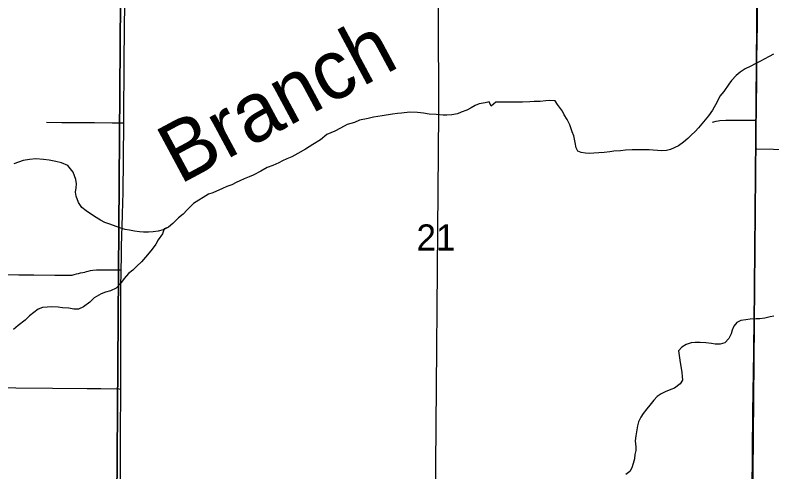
# Model space of a CAD drawing. Extents: x 0 to 34, y 0 to 22.
# Drawn here: x 6.452 to 7.662, y 16.502 to 17.233 of the extents above; entities that cross this region are included whole.
import ezdxf

# ---------------------------------------------------------------- set-up
doc = ezdxf.new("R2010")
doc.units = 0
for name, color, linetype in [('GM_X_County_Road', 7, 'Continuous'), ('GM_X_Major_River', 7, 'Continuous'), ('GM_X_Major_River_Text', 7, 'Continuous'), ('GM_X_Minor_River', 7, 'Continuous'), ('GM_X_Rail_Line', 7, 'Continuous'), ('GM_X_Section', 7, 'Continuous'), ('GM_X_Section_Text', 7, 'Continuous'), ('GM_X_Township_Road', 7, 'Continuous')]:
    doc.layers.add(name, color=color, linetype=linetype)

msp = doc.modelspace()

# ---------------------------------------------------------------- linework, layer by layer
at = {"layer": 'GM_X_County_Road'}
for points in [[(7.6367, 17.065), (7.6366, 17.0726), (7.6373, 17.1192), (7.6377, 17.1626), (7.6387, 17.2186), (7.6392, 17.3115), (7.6396, 17.3767), (7.6402, 17.4023)], [(7.6362, 17.0194), (7.6362, 17.0263), (7.6367, 17.065)], [(7.6291, 16.3875), (7.6291, 16.399), (7.63, 16.4704), (7.6314, 16.5977), (7.6327, 16.694), (7.6332, 16.7499), (7.6341, 16.8182), (7.6347, 16.8648), (7.6351, 16.9176), (7.6358, 16.9672), (7.6359, 16.9859), (7.6362, 17.0194)]]:
    msp.add_lwpolyline(points, dxfattribs=at)
at = {"layer": 'GM_X_Major_River'}
for points in [[(7.657, 17.167), (7.6491, 17.1625), (7.6434, 17.1594), (7.6362, 17.1557), (7.6271, 17.1511), (7.6187, 17.1469), (7.6108, 17.1416), (7.6043, 17.1363), (7.5968, 17.1283), (7.5926, 17.1226), (7.585, 17.1109), (7.5786, 17.1033), (7.574, 17.0945), (7.5664, 17.0812), (7.56, 17.0718), (7.555, 17.0653), (7.5497, 17.0589), (7.5441, 17.0528), (7.5387, 17.0471), (7.5327, 17.041), (7.527, 17.0357), (7.5205, 17.03), (7.5122, 17.0239), (7.4993, 17.0179), (7.4932, 17.0163), (7.4857, 17.016), (7.4785, 17.0164), (7.4716, 17.0171), (7.4652, 17.0175), (7.4383, 17.0175), (7.4273, 17.0168), (7.4193, 17.016), (7.4091, 17.0153), (7.4023, 17.0145), (7.3932, 17.0134), (7.3848, 17.0126), (7.3769, 17.0122), (7.3697, 17.0119), (7.3636, 17.0123), (7.3568, 17.0134), (7.3511, 17.0153), (7.3484, 17.021), (7.3469, 17.0294), (7.3447, 17.04), (7.342, 17.0465), (7.3386, 17.0575), (7.3341, 17.0662), (7.3295, 17.0738), (7.3269, 17.0795), (7.3189, 17.0901), (7.3151, 17.0962), (7.306, 17.0966), (7.2999, 17.0959), (7.2912, 17.0951), (7.2817, 17.0947), (7.2745, 17.0944), (7.2628, 17.094), (7.2325, 17.094), (7.22, 17.0936), (7.2128, 17.0876), (7.2093, 17.0944), (7.2029, 17.0925), (7.1934, 17.091), (7.1874, 17.0883), (7.1809, 17.0845), (7.1737, 17.0811), (7.165, 17.0777), (7.1589, 17.0754), (7.1498, 17.0735), (7.1419, 17.0732), (7.1358, 17.0732), (7.1248, 17.0739), (7.1134, 17.0747), (7.1043, 17.0762), (7.0949, 17.0774), (7.0827, 17.0778), (7.0691, 17.0763), (7.063, 17.0755), (7.0551, 17.0744), (7.0384, 17.0721), (7.0316, 17.071), (7.0244, 17.0698), (7.016, 17.0679), (7.0024, 17.0649), (6.994, 17.0611), (6.9827, 17.0581), (6.972, 17.052), (6.9629, 17.0475), (6.9497, 17.0422), (6.9398, 17.0338), (6.9273, 17.0262), (6.9159, 17.0186), (6.9038, 17.0118), (6.8939, 17.0065), (6.886, 17.0031), (6.8788, 16.9997), (6.8731, 16.997), (6.8636, 16.9925), (6.8545, 16.9894), (6.8443, 16.9833), (6.8321, 16.9769)], [(7.6642, 17.1705), (7.657, 17.167)], [(6.7609, 16.9466), (6.737, 16.9318), (6.7264, 16.9215), (6.7203, 16.9147), (6.7127, 16.9086), (6.7036, 16.8999), (6.6968, 16.8938), (6.6881, 16.8896), (6.6805, 16.8874), (6.6722, 16.8862), (6.6646, 16.8859), (6.6566, 16.8859), (6.6502, 16.8866), (6.6426, 16.8874), (6.6343, 16.8889), (6.6274, 16.8901), (6.6206, 16.8923), (6.613, 16.895), (6.6028, 16.8988), (6.5952, 16.9015), (6.588, 16.9053), (6.5785, 16.911), (6.5649, 16.9201), (6.5584, 16.9254), (6.5528, 16.9334), (6.549, 16.9433), (6.5482, 16.9501), (6.549, 16.957), (6.5494, 16.9634), (6.5486, 16.9699), (6.5444, 16.9817), (6.5357, 16.9923), (6.5259, 16.9965), (6.5168, 16.9988), (6.5062, 17.001), (6.4967, 17.0022), (6.4845, 17.003), (6.4743, 17.0022), (6.4645, 17.0007), (6.4493, 16.995)], [(6.8321, 16.9769), (6.8257, 16.9742), (6.8177, 16.9712), (6.8109, 16.9682), (6.8052, 16.9655), (6.798, 16.9617), (6.7901, 16.9587), (6.7829, 16.9557), (6.7677, 16.9488), (6.7609, 16.9466)]]:
    msp.add_lwpolyline(points, dxfattribs=at)
at = {"layer": 'GM_X_Minor_River'}
for points in [[(6.6943, 16.8926), (6.69, 16.8912), (6.6869, 16.8832), (6.6805, 16.8737), (6.6767, 16.8669), (6.6706, 16.8585), (6.6631, 16.8494), (6.6536, 16.8384), (6.646, 16.8312), (6.6395, 16.8251), (6.6327, 16.8198), (6.6259, 16.8118), (6.6202, 16.8035), (6.613, 16.7963), (6.6039, 16.7921), (6.5959, 16.7898), (6.5891, 16.7872), (6.5781, 16.7807), (6.5709, 16.7739), (6.5611, 16.7663), (6.5531, 16.7625), (6.5455, 16.7629), (6.5372, 16.764), (6.5273, 16.7648), (6.5201, 16.7656), (6.5103, 16.7663), (6.4951, 16.7652), (6.4883, 16.7625), (6.4746, 16.7519), (6.4678, 16.7451), (6.4564, 16.7367), (6.4488, 16.7303)], [(7.6649, 16.7515), (7.6588, 16.7504), (7.6505, 16.7485), (7.6425, 16.7473), (7.6365, 16.7473), (7.627, 16.7466), (7.6198, 16.7455), (7.6118, 16.7443), (7.6058, 16.7413)], [(7.6058, 16.7413), (7.6008, 16.7352), (7.5982, 16.7291), (7.5963, 16.7234), (7.5929, 16.7155), (7.5864, 16.709), (7.5788, 16.7064), (7.5709, 16.7064), (7.5648, 16.7075), (7.5561, 16.7087), (7.547, 16.7094), (7.539, 16.7094), (7.5326, 16.7087), (7.5246, 16.706), (7.5174, 16.7018), (7.5125, 16.6958), (7.5152, 16.6772), (7.5167, 16.6684), (7.5174, 16.6612), (7.5182, 16.6548), (7.5186, 16.6491), (7.5151, 16.6434), (7.5057, 16.6365), (7.5, 16.6339), (7.4909, 16.6305), (7.4844, 16.6274), (7.4784, 16.6229), (7.4731, 16.6172), (7.4662, 16.6092), (7.4617, 16.6031), (7.4556, 16.5956), (7.4522, 16.5899), (7.4484, 16.5823), (7.4465, 16.5762), (7.4458, 16.5694), (7.4439, 16.5602), (7.4431, 16.5519), (7.4438, 16.5424), (7.4438, 16.5367), (7.4423, 16.5299), (7.4419, 16.5234), (7.4397, 16.5158), (7.4374, 16.509), (7.4344, 16.5029), (7.4279, 16.498)]]:
    msp.add_lwpolyline(points, dxfattribs=at)
at = {"layer": 'GM_X_Rail_Line'}
msp.add_lwpolyline([(7.1325, 17.6042), (7.1272, 17.4005), (7.1287, 17.0765), (7.1229, 16.3878), (7.1287, 15.8668)], dxfattribs=at)
at = {"layer": 'GM_X_Section'}
for points in [[(6.6213, 17.4032), (6.6138, 16.3837), (5.6285, 16.3977), (5.6487, 17.4026)], [(7.639, 17.3962), (7.6303, 16.3805), (6.6138, 16.3837), (6.6213, 17.4032)], [(7.639, 17.3962), (8.6426, 17.3907), (8.6324, 16.375), (7.6303, 16.3805)]]:
    msp.add_lwpolyline(points, close=True, dxfattribs=at)
at = {"layer": 'GM_X_Township_Road'}
msp.add_line((6.6212, 16.8256), (6.6215, 16.8465), dxfattribs=at)
for points in [[(6.6254, 17.0608), (6.6254, 17.0623), (6.6258, 17.1617), (6.6267, 17.255), (6.6271, 17.2891), (6.6283, 17.3762), (6.6286, 17.3964)], [(7.5664, 17.0618), (7.5724, 17.0635), (7.5755, 17.0642), (7.5786, 17.0645), (7.588, 17.0649), (7.6101, 17.0648), (7.6367, 17.065)], [(6.5017, 17.0617), (6.5262, 17.0615), (6.5786, 17.0612), (6.6065, 17.0609), (6.622, 17.0609), (6.6254, 17.0608)], [(6.6237, 16.9346), (6.6241, 16.9473), (6.6254, 17.0608)], [(7.6362, 17.0194), (7.6376, 17.0193), (7.7175, 17.0174), (7.7178, 17.0121)], [(6.6215, 16.8465), (6.6218, 16.8634), (6.6231, 16.9131), (6.6237, 16.9346)], [(6.3788, 16.8186), (6.429, 16.818), (6.4574, 16.8176), (6.4812, 16.8174), (6.5152, 16.8169), (6.5336, 16.8169), (6.5368, 16.8168), (6.5402, 16.8169), (6.5429, 16.8173), (6.5459, 16.8179), (6.5499, 16.8192), (6.553, 16.8199), (6.5562, 16.8207), (6.56, 16.8212), (6.5628, 16.8218), (6.5658, 16.8227), (6.5684, 16.8235), (6.572, 16.8246), (6.5755, 16.8253), (6.5817, 16.8258), (6.5911, 16.8258), (6.6184, 16.8256), (6.6212, 16.8256)], [(6.6203, 16.6349), (6.6204, 16.6676), (6.6207, 16.6924), (6.6207, 16.795), (6.6212, 16.8256)], [(6.2717, 16.6352), (6.2769, 16.6364), (6.2809, 16.6373), (6.2833, 16.6377), (6.2855, 16.638), (6.2884, 16.6382), (6.2917, 16.6382), (6.2959, 16.6383), (6.3033, 16.6382), (6.3157, 16.6378), (6.3625, 16.6375), (6.4121, 16.6372), (6.4529, 16.6367), (6.5111, 16.6361), (6.5667, 16.6358), (6.5886, 16.6356), (6.6178, 16.635), (6.6203, 16.6349)], [(6.6194, 16.3862), (6.6199, 16.4282), (6.6199, 16.4904), (6.62, 16.5619), (6.6203, 16.6349)]]:
    msp.add_lwpolyline(points, dxfattribs=at)

# ---------------------------------------------------------------- texts
at = {"layer": 'GM_X_Major_River_Text'}
msp.add_text('Branch', height=0.09476, rotation=28.208, dxfattribs=at).set_placement((6.7147, 16.9616))
at = {"layer": 'GM_X_Section_Text'}
msp.add_text('21', height=0.04186, rotation=0, dxfattribs=at).set_placement((7.0933, 16.8564))

doc.saveas('drawing.dxf')
